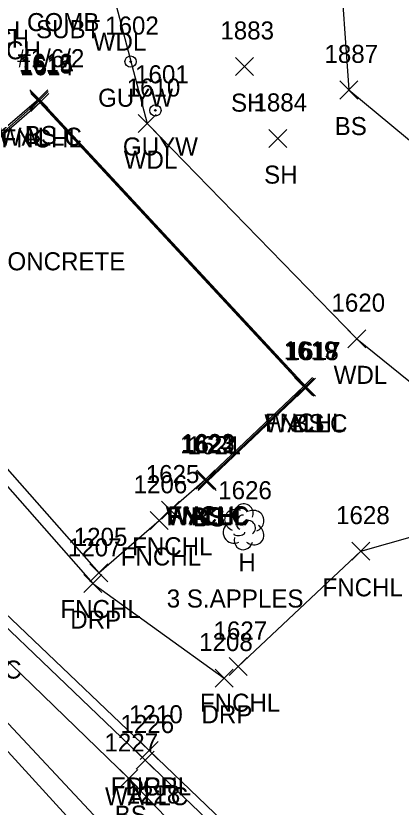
# Model space of a CAD drawing. Extents: x 1647133 to 1649138, y 411736 to 414924.
# Drawn here: x 1648834.8 to 1648877.6, y 411978.2 to 412065.9 of the extents above; entities that cross this region are included whole.
import ezdxf

# ---------------------------------------------------------------- set-up
doc = ezdxf.new("R2010")
doc.units = 0
for name, color, linetype in [('C_C', 7, 'Continuous'), ('D_A', 7, 'Continuous'), ('L_A', 7, 'Continuous'), ('L_C', 7, 'Continuous'), ('L_I', 7, 'Continuous'), ('L_TIC', 7, 'Continuous'), ('LAWA', 7, 'Continuous'), ('LELB', 7, 'Continuous'), ('LFNC', 7, 'Continuous'), ('LTD', 7, 'Continuous'), ('LW', 7, 'Continuous'), ('PET', 7, 'Continuous'), ('R_A', 7, 'Continuous'), ('R_I', 7, 'Continuous'), ('R_TIC', 7, 'Continuous'), ('RDP', 7, 'Continuous'), ('U_A', 7, 'Continuous'), ('U_C', 7, 'Continuous'), ('U_I', 7, 'Continuous'), ('UPGW', 7, 'Continuous')]:
    doc.layers.add(name, color=color, linetype=linetype)

msp = doc.modelspace()

# ---------------------------------------------------------------- linework, layer by layer
at = {"layer": 'L_TIC'}
for points in [[(1648859.22, 412059.261), (1648861.22, 412061.261)], [(1648861.22, 412059.261), (1648859.22, 412061.261)], [(1648870.765, 412056.665), (1648872.765, 412058.665)], [(1648872.765, 412056.665), (1648870.765, 412058.665)], [(1648836.396, 412055.676), (1648838.396, 412057.676)], [(1648838.396, 412055.676), (1648836.396, 412057.676)], [(1648836.422, 412055.488), (1648838.422, 412057.488)], [(1648838.422, 412055.488), (1648836.422, 412057.488)], [(1648836.504, 412055.292), (1648838.504, 412057.292)], [(1648838.504, 412055.292), (1648836.504, 412057.292)], [(1648848.396, 412052.935), (1648850.396, 412054.935)], [(1648850.396, 412052.935), (1648848.396, 412054.935)], [(1648862.892, 412051.288), (1648864.892, 412053.288)], [(1648864.892, 412051.288), (1648862.892, 412053.288)], [(1648871.677, 412029.098), (1648873.677, 412031.098)], [(1648873.677, 412029.098), (1648871.677, 412031.098)], [(1648865.733, 412023.803), (1648867.733, 412025.803)], [(1648867.733, 412023.803), (1648865.733, 412025.803)], [(1648865.88, 412023.72), (1648867.88, 412025.72)], [(1648867.88, 412023.72), (1648865.88, 412025.72)], [(1648866.07, 412023.741), (1648868.07, 412025.741)], [(1648868.07, 412023.741), (1648866.07, 412025.741)], [(1648854.805, 412013.42), (1648856.805, 412015.42)], [(1648856.805, 412013.42), (1648854.805, 412015.42)], [(1648854.805, 412013.42), (1648856.805, 412015.42)], [(1648856.805, 412013.42), (1648854.805, 412015.42)], [(1648854.925, 412013.54), (1648856.925, 412015.54)], [(1648856.925, 412013.54), (1648854.925, 412015.54)], [(1648854.925, 412013.54), (1648856.925, 412015.54)], [(1648856.925, 412013.54), (1648854.925, 412015.54)], [(1648855.029, 412013.417), (1648857.029, 412015.417)], [(1648857.029, 412013.417), (1648855.029, 412015.417)], [(1648855.061, 412013.298), (1648857.061, 412015.298)], [(1648857.061, 412013.298), (1648855.061, 412015.298)], [(1648850.991, 412010.105), (1648852.991, 412012.105)], [(1648852.991, 412010.105), (1648850.991, 412012.105)], [(1648850.991, 412010.105), (1648852.991, 412012.105)], [(1648852.991, 412010.105), (1648850.991, 412012.105)], [(1648849.733, 412008.972), (1648851.733, 412010.972)], [(1648851.733, 412008.972), (1648849.733, 412010.972)], [(1648849.733, 412008.972), (1648851.733, 412010.972)], [(1648851.733, 412008.972), (1648849.733, 412010.972)], [(1648872.103, 412005.555), (1648874.103, 412007.555)], [(1648874.103, 412005.555), (1648872.103, 412007.555)], [(1648843.039, 412003.151), (1648845.039, 412005.151)], [(1648845.039, 412003.151), (1648843.039, 412005.151)], [(1648858.506, 411992.771), (1648860.506, 411994.771)], [(1648860.506, 411992.771), (1648858.506, 411994.771)], [(1648848.624, 411983.488), (1648850.624, 411985.488)], [(1648850.624, 411983.488), (1648848.624, 411985.488)], [(1648848.198, 411982.406), (1648850.198, 411984.406)], [(1648850.198, 411982.406), (1648848.198, 411984.406)], [(1648846.368, 411980.365), (1648848.368, 411982.365)], [(1648848.368, 411980.365), (1648846.368, 411982.365)]]:
    msp.add_lwpolyline(points, dxfattribs=at)
at = {"layer": 'LAWA'}
msp.add_lwpolyline([(1648847.547, 412073.481), (1648845.956, 412067.029), (1648849.396, 412053.935), (1648872.677, 412030.098), (1648893.028, 412013.641), (1648901.106, 412007.99), (1648905.808, 411990.864)], dxfattribs=at)
at = {"layer": 'LELB'}
for points in [[(1648870.706, 412072.868), (1648871.765, 412057.665), (1648894.095, 412039.166), (1648930.858, 412008.261)], [(1648825.765, 412046.698), (1648837.396, 412056.676), (1648867.07, 412024.741), (1648856.061, 412014.298), (1648855.805, 412014.42)], [(1648820.342, 412002.003), (1648856.58, 411963.322), (1648864.038, 411954.98)], [(1648830.728, 411997.439), (1648847.368, 411981.365), (1648862.655, 411965.419), (1648868.166, 411960.17)]]:
    msp.add_lwpolyline(points, dxfattribs=at)
at = {"layer": 'LFNC'}
for points in [[(1648826.315, 412046.566), (1648837.504, 412056.292), (1648866.733, 412024.803), (1648855.925, 412014.54), (1648855.805, 412014.42), (1648851.991, 412011.105)], [(1648826.235, 412046.371), (1648815.427, 412036.549), (1648844.039, 412004.151), (1648850.733, 412009.972)], [(1648859.506, 411993.771), (1648873.103, 412006.555), (1648891.575, 412011.791), (1648898.662, 412005.053), (1648901.331, 411987.941)], [(1648850.733, 412009.972), (1648851.991, 412011.105)], [(1648849.624, 411984.488), (1648865.02, 411969.719), (1648897.223, 411938.969), (1648929.213, 411910.119)]]:
    msp.add_lwpolyline(points, dxfattribs=at)
at = {"layer": 'LTD'}
msp.add_line((1648860.087, 412009.316), (1648860.087, 412009.316), dxfattribs=at)
msp.add_line((1648860.087, 412009.316), (1648860.087, 412009.316), dxfattribs=at)
msp.add_arc((1648860.134, 412010.75), 1.047, 335.52715, 180.95627, dxfattribs=at)
for centre, major_axis, ratio, start_param, end_param in [((1648859.296, 412009.982), (1.21, -0.512), 0.895232, 1.570796, 4.712389), ((1648861.129, 412009.899), (-1.141, -0.483), 0.949671, 1.570796, 4.712389), ((1648859.879, 412009.774), (-0.208, -0.792), 0.645439, 3.141593, 6.283185), ((1648860.587, 412009.149), (-0.5, 0.667), 0.989748, 3.141593, 6.283185), ((1648859.004, 412008.607), (0.584, -1.042), 0.959034, 3.141593, 6.283185), ((1648861.087, 412008.483), (-1.09, 0.792), 0.841452, 1.570796, 4.712389), ((1648860.088, 412007.816), (0.265, 1.061), 0.942809, 1.570796, 4.712389), ((1648859.629, 412008.566), (-0.625, -0.083), 0.423636, 0, 3.141593)]:
    msp.add_ellipse(centre, major_axis=major_axis, ratio=ratio, start_param=start_param, end_param=end_param, dxfattribs=at)
at = {"layer": 'LW'}
for points in [[(1648826.222, 412046.61), (1648837.422, 412056.488), (1648866.88, 412024.72), (1648856.029, 412014.417), (1648855.925, 412014.54)], [(1648830.728, 411997.439), (1648820.132, 412007.636), (1648821.905, 412009.475), (1648849.198, 411983.406), (1648865.538, 411967.762), (1648896.838, 411937.49), (1648928.08, 411909.127), (1648926.287, 411907.011), (1648925.128, 411907.94)]]:
    msp.add_lwpolyline(points, dxfattribs=at)
at = {"layer": 'PET'}
msp.add_lwpolyline([(1648818.001, 412063.558), (1648810.494, 412053.715), (1648791.901, 412040.154), (1648791.666, 412033.115), (1648794.121, 412026.773), (1648798.944, 412021.85), (1648819.062, 412000.668), (1648854.228, 411962.165), (1648865.258, 411946.896), (1648874.312, 411932.811), (1648885.803, 411915.985), (1648895.792, 411902.999)], dxfattribs=at)
at = {"layer": 'R_TIC'}
for points in [[(1648842.392, 412001.982), (1648844.392, 412003.982)], [(1648844.392, 412001.982), (1648842.392, 412003.982)], [(1648856.948, 411991.491), (1648858.948, 411993.491)], [(1648858.948, 411991.491), (1648856.948, 411993.491)], [(1648848.624, 411983.488), (1648850.624, 411985.488)], [(1648850.624, 411983.488), (1648848.624, 411985.488)]]:
    msp.add_lwpolyline(points, dxfattribs=at)
at = {"layer": 'RDP'}
for points in [[(1648814.484, 412035.767), (1648843.392, 412002.982), (1648857.948, 411992.491)], [(1648798.944, 412021.85), (1648802.042, 412026.244), (1648803.97, 412028.271), (1648822.321, 412010.459), (1648849.624, 411984.488)]]:
    msp.add_lwpolyline(points, dxfattribs=at)
at = {"layer": 'UPGW'}
for centre, radius in [((1648847.572, 412060.806), 0.625), ((1648847.572, 412060.806), 0.0833), ((1648850.325, 412055.402), 0.625), ((1648850.325, 412055.402), 0.0833)]:
    msp.add_circle(centre, radius, dxfattribs=at)

# ---------------------------------------------------------------- texts
at = {"layer": 'C_C'}
msp.add_text('CHISELED SQUARE IN CONCRETE', height=2, dxfattribs=at).set_placement((1648802.408, 412037.682))
at = {"layer": 'D_A'}
for p in [(1648827.154, 412063.276), (1648828.141, 412062.359), (1648829.456, 412061.063)]:
    msp.add_text('DITCH', height=2, dxfattribs=at).set_placement(p)
at = {"layer": 'L_A'}
for s, p in [('WDL', (1648843.373, 412062.029)), ('SH', (1648858.708, 412055.261)), ('BS', (1648870.206, 412052.665)), ('BS', (1648835.837, 412051.676)), ('WALLC', (1648832.957, 412051.488)), ('FNCHL', (1648833.252, 412051.292)), ('WDL', (1648846.814, 412048.935)), ('SH', (1648862.38, 412047.288)), ('WDL', (1648870.094, 412025.098)), ('WALLC', (1648862.416, 412019.72)), ('FNCHL', (1648862.481, 412019.803)), ('BS', (1648865.511, 412019.741)), ('WALLC', (1648851.46, 412009.54)), ('FNCHL', (1648851.673, 412009.54)), ('WALLC', (1648851.564, 412009.417)), ('FNCHL', (1648851.553, 412009.42)), ('BS', (1648854.246, 412009.42)), ('BS', (1648854.502, 412009.298)), ('FNCHL', (1648847.739, 412006.105)), ('FNCHL', (1648847.739, 412006.105)), ('FNCHL', (1648846.481, 412004.972)), ('FNCHL', (1648846.481, 412004.972)), ('H', (1648859.52, 412004.316)), ('FNCHL', (1648868.851, 412001.555)), ('FNCHL', (1648839.787, 411999.151)), ('WALLC', (1648826.263, 411992.439)), ('FNCHL', (1648855.254, 411988.771)), ('FNCHL', (1648845.372, 411979.488)), ('WALLC', (1648844.733, 411978.406)), ('BS', (1648845.809, 411976.365))]:
    msp.add_text(s, height=2, dxfattribs=at).set_placement(p)
at = {"layer": 'L_C'}
msp.add_text('3 S.APPLES', height=2, dxfattribs=at).set_placement((1648851.583, 412000.316))
at = {"layer": 'L_I'}
for s, p in [('1883', (1648857.527, 412063.261)), ('1887', (1648869.072, 412060.665)), ('1616', (1648835.167, 412059.676)), ('1615', (1648835.249, 412059.488)), ('1614', (1648835.331, 412059.292)), ('1610', (1648847.136, 412056.935)), ('1884', (1648861.199, 412055.288)), ('1620', (1648869.85, 412033.098)), ('1619', (1648864.552, 412027.803)), ('1618', (1648864.707, 412027.72)), ('1617', (1648864.896, 412027.741)), ('1624', (1648853.065, 412017.42)), ('1624', (1648853.065, 412017.42)), ('1623', (1648853.184, 412017.54)), ('1623', (1648853.184, 412017.54)), ('1622', (1648853.289, 412017.417)), ('1621', (1648853.888, 412017.298)), ('1625', (1648849.251, 412014.105)), ('1625', (1648849.251, 412014.105)), ('1206', (1648847.906, 412012.972)), ('1206', (1648847.906, 412012.972)), ('1626', (1648857.292, 412012.316)), ('1628', (1648870.363, 412009.555)), ('1205', (1648841.267, 412007.151)), ('1627', (1648856.766, 411996.771)), ('1210', (1648847.412, 411987.488)), ('1226', (1648846.45, 411986.406)), ('1227', (1648844.675, 411984.365)), ('1228', (1648847.13, 411978.592))]:
    msp.add_text(s, height=2, dxfattribs=at).set_placement(p)
at = {"layer": 'R_A'}
for p in [(1648840.88, 411997.982), (1648855.436, 411987.491), (1648847.112, 411979.488)]:
    msp.add_text('DRP', height=2, dxfattribs=at).set_placement(p)
at = {"layer": 'R_I'}
for s, p in [('1207', (1648840.62, 412005.982)), ('1208', (1648855.176, 411995.491)), ('1210', (1648847.412, 411987.488))]:
    msp.add_text(s, height=2, dxfattribs=at).set_placement(p)
at = {"layer": 'U_A'}
for s, p in [('COMB', (1648836.086, 412064.188)), ('SUBT', (1648837.084, 412063.404)), ('GUYW', (1648843.966, 412055.806)), ('GUYW', (1648846.719, 412050.402))]:
    msp.add_text(s, height=2, dxfattribs=at).set_placement(p)
at = {"layer": 'U_C'}
msp.add_text('#1/6/2', height=2, dxfattribs=at).set_placement((1648835.008, 412060.188))
at = {"layer": 'U_I'}
for s, p in [('1602', (1648844.753, 412063.806)), ('1601', (1648848.073, 412058.402))]:
    msp.add_text(s, height=2, dxfattribs=at).set_placement(p)

doc.saveas('drawing.dxf')
